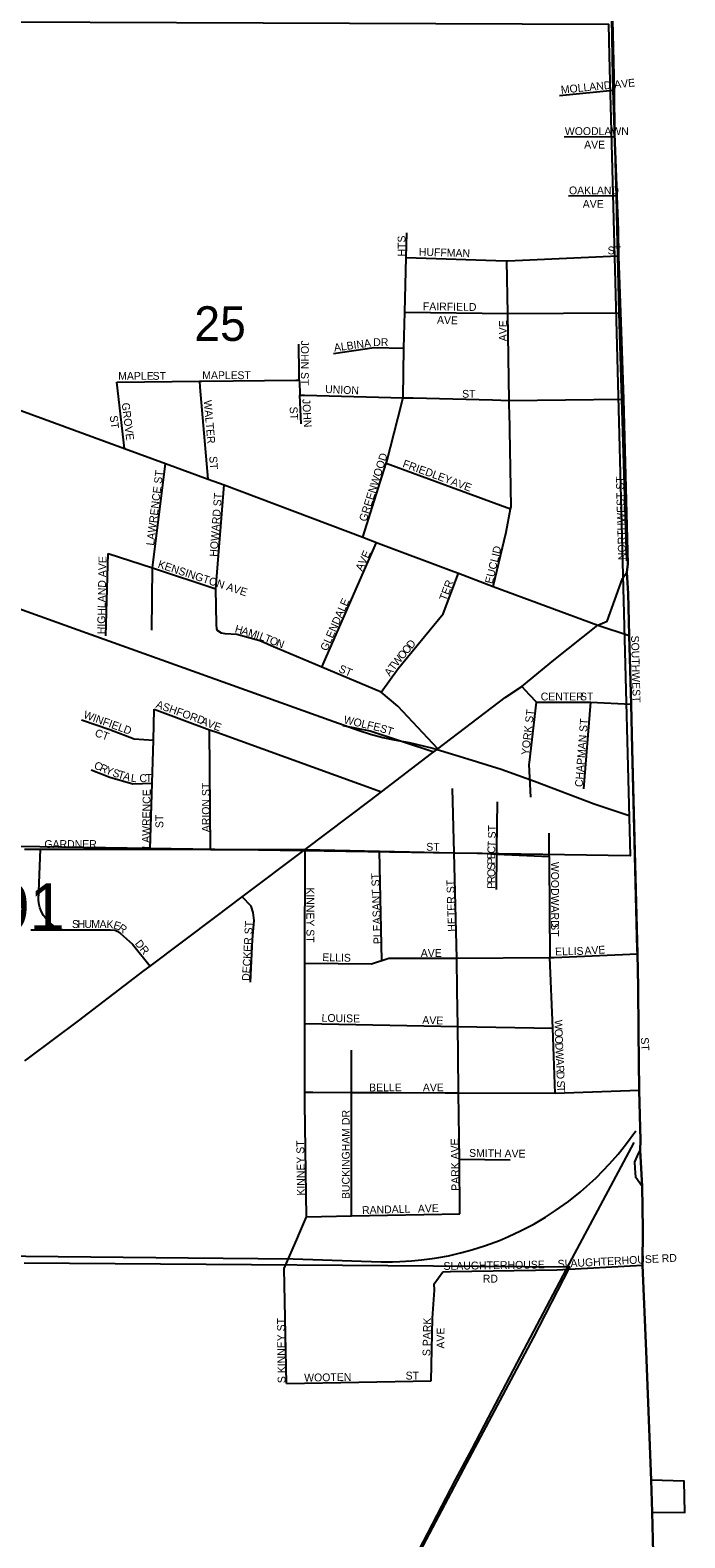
# Model space of a CAD drawing. Extents: x 1588073 to 2013523, y 1090242 to 1357120.
# Drawn here: x 1870959 to 1875138, y 1186996 to 1196618 of the extents above; entities that cross this region are included whole.
import ezdxf

# ---------------------------------------------------------------- set-up
doc = ezdxf.new("R2010")
doc.units = 0
for name, color, linetype in [('GM_X_Adjacent_County', 7, 'Continuous'), ('GM_X_City_Street', 7, 'Continuous'), ('GM_X_City_Street_Text', 7, 'Continuous'), ('GM_X_Corporation', 7, 'Continuous'), ('GM_X_County', 7, 'Continuous'), ('GM_X_County_Road_Text', 7, 'Continuous'), ('GM_X_Rail_Line', 7, 'Continuous'), ('GM_X_Section', 7, 'Continuous'), ('GM_X_Section_Text', 7, 'Continuous'), ('GM_X_State_Route', 7, 'Continuous'), ('GM_X_Township', 7, 'Continuous'), ('GM_X_Township_Subdivision', 7, 'Continuous'), ('GM_X_Township_Subdivision_Text', 7, 'Continuous'), ('GM_X_US_Route', 7, 'Continuous')]:
    doc.layers.add(name, color=color, linetype=linetype)

msp = doc.modelspace()

# ---------------------------------------------------------------- linework, layer by layer
at = {"layer": 'GM_X_Adjacent_County'}
msp.add_lwpolyline([(1874941.8, 1186640.9), (1874928.7, 1187160.7), (1874923.1, 1187364.9), (1874891.8, 1188188.1), (1874868.6, 1188735.8), (1874869, 1188969.3), (1874865.1, 1189239.2), (1874853.3, 1189471.1), (1874854.7, 1189533.5), (1874845.4, 1189851), (1874842.8, 1190228.3), (1874840.7, 1190513.7), (1874834.9, 1190722.6), (1874802.4, 1192031.4), (1874794.6, 1192317.6), (1874782.4, 1192755.6), (1874775.3, 1193023.2), (1874768.5, 1193158.1), (1874773.4, 1193209.6), (1874747.1, 1194263.8), (1874727.1, 1194819.2), (1874714.3, 1195175.2), (1874711.9, 1195341.1), (1874703.6, 1195559.3), (1874702.4, 1195623.6), (1874689.1, 1195958.2), (1874687.1, 1196230.8), (1874684.9, 1196324.1), (1874676.2, 1196684.8)], dxfattribs=at)
at = {"layer": 'GM_X_City_Street'}
for points in [[(1874768, 1193232), (1874736.3, 1194263.9), (1874719.1, 1194813.2), (1874709.8, 1195178.2), (1874705.4, 1195348.6), (1874700.7, 1195562.6), (1874698.8, 1195622.6), (1874690.4, 1195938.5), (1874689.3, 1195978.9), (1874681.4, 1196235.5), (1874678.7, 1196322.5), (1874670.9, 1196695.4)], [(1874338.9, 1196200.5), (1874681.4, 1196235.5)], [(1874368.4, 1195937.4), (1874690.4, 1195938.5)], [(1874396.1, 1195559.7), (1874700.7, 1195562.6)], [(1873336.3, 1194259.6), (1873339.6, 1194272.3), (1873340.5, 1194275.7), (1873344.2, 1194587.9), (1873350.3, 1194817.8), (1873359.4, 1195166.8), (1873363.6, 1195323.6)], [(1873359.4, 1195166.8), (1873996.2, 1195146.7), (1874001.5, 1195146.5), (1874007.8, 1195146.8)], [(1874017.6, 1194205.5), (1874016.7, 1194255.2), (1874007.3, 1194808.7), (1874001.5, 1195146.5)], [(1874007.8, 1195146.8), (1874709.8, 1195178.2)], [(1873350.3, 1194817.8), (1874007.3, 1194808.7), (1874719.1, 1194813.2)], [(1872676.5, 1194383.8), (1872675.9, 1194429.6), (1872673.6, 1194613.2)], [(1872894.3, 1194554.9), (1873155.3, 1194592.9), (1873344.2, 1194587.9)], [(1871513, 1194371), (1872042.1, 1194378.2)], [(1871561.6, 1193948.1), (1871513, 1194371)], [(1872096.1, 1193752.3), (1872043.1, 1194340.6), (1872042.1, 1194378.2), (1872053.9, 1194378.3)], [(1872053.9, 1194378.3), (1872654.9, 1194383.6), (1872676.5, 1194383.8), (1872677.3, 1194366.5)], [(1872677.3, 1194366.5), (1872680.4, 1194299.5), (1872680.9, 1194288.9), (1872710, 1194288.2)], [(1872689.4, 1194105.2), (1872680.9, 1194288.9)], [(1872710, 1194288.2), (1873339.6, 1194272.3), (1873367.8, 1194271.6), (1873403.1, 1194270.7)], [(1873083.5, 1193383), (1873231.2, 1193853.9), (1873236.1, 1193865.9), (1873328.9, 1194230.2), (1873336.3, 1194259.6)], [(1873403.1, 1194270.7), (1873909.9, 1194257.9), (1874016.7, 1194255.2), (1874736.3, 1194263.9)], [(1873915.3, 1193068), (1873997.9, 1193413.6), (1874025.7, 1193562.3), (1874028.3, 1193576.3), (1874017.9, 1194188.4), (1874017.6, 1194205.5)], [(1871736.5, 1192788.6), (1871740.2, 1193185.8), (1871823.2, 1193851.6)], [(1873231.2, 1193853.9), (1874025.7, 1193562.3)], [(1872149.4, 1192827.8), (1872144.9, 1193053.3), (1872197.4, 1193716.2)], [(1871441.4, 1192752.6), (1871456.5, 1193278.7)], [(1871456.5, 1193278.7), (1871740.2, 1193185.8), (1872144.9, 1193053.3)], [(1872820.3, 1192553.2), (1873169.8, 1193348.9)], [(1873200.5, 1192392.7), (1873307.6, 1192544.6), (1873594.2, 1192892.3), (1873692.5, 1193153.3)], [(1874582.2, 1192821.4), (1874641.4, 1192845.6), (1874739.4, 1193119.3), (1874768.3, 1193159.8)], [(1872512.3, 1192682.8), (1872424.5, 1192719.8), (1872278.1, 1192760.5), (1872203.9, 1192764.8), (1872179.8, 1192768.9), (1872157.4, 1192784.1), (1872150, 1192794.3), (1872149.4, 1192827.8)], [(1874834.2, 1190748.9), (1874802.4, 1192031.4), (1874794.6, 1192317.6), (1874782.4, 1192755.6)], [(1873560.5, 1192032), (1873305.5, 1192304.7), (1873200.5, 1192392.7), (1872820.3, 1192553.2), (1872537.9, 1192672), (1872512.3, 1192682.8)], [(1874098, 1192428.8), (1874144.3, 1192378.4), (1874190.4, 1192330.1), (1874213.7, 1192330)], [(1874146, 1191944.3), (1874190.4, 1192330.1)], [(1874213.7, 1192330), (1874538.1, 1192328.9), (1874794.6, 1192317.6)], [(1874492.3, 1191776.8), (1874538.1, 1192328.9)], [(1871285.7, 1192216.6), (1871468.3, 1192154.2), (1871622.7, 1192095.9), (1871745.8, 1192087.3)], [(1871725.6, 1191390.4), (1871737.9, 1191812.6), (1871745.8, 1192087.3), (1871751.5, 1192284.6)], [(1871751.5, 1192284.6), (1872104.5, 1192153.8), (1872149.6, 1192137.5), (1872150.6, 1192137.1)], [(1872111, 1191390), (1872104.5, 1192153.8)], [(1872150.6, 1192137.1), (1873200.6, 1191756.6)], [(1872955.6, 1192179.4), (1873130.2, 1192147.1), (1873535.1, 1192012.7)], [(1874154.9, 1191722.8), (1874144.7, 1191932.5), (1874146, 1191944.3)], [(1871347.3, 1191897.3), (1871467.6, 1191851), (1871614.1, 1191808.7), (1871737.9, 1191812.6)], [(1873683.2, 1190695), (1873665.8, 1191368.6), (1873655.3, 1191779.3)], [(1873938.2, 1191388.3), (1873938.2, 1191388.3), (1873942.2, 1191692.8)], [(1874271.9, 1191345), (1874270.9, 1191493.8)], [(1870923.2, 1191391.2), (1871025.1, 1191391.1), (1871725.6, 1191390.4), (1872111, 1191390), (1872714.4, 1191389.4)], [(1871162.5, 1190877.3), (1871138.7, 1190885), (1871114.6, 1190898), (1871084.9, 1190920.1), (1871062.8, 1190942.8), (1871043.8, 1190968.9), (1871033.5, 1190987.3), (1871027, 1191003), (1871020.6, 1191019.3), (1871016.1, 1191036), (1871011.3, 1191066.6), (1871025.1, 1191391.1)], [(1872712.2, 1190054.2), (1872712.2, 1190060), (1872712.6, 1190278), (1872713.2, 1190663.5), (1872714.4, 1191389.4)], [(1872714.4, 1191389.4), (1873189, 1191379), (1873665.8, 1191368.6), (1873844.4, 1191364.7), (1873937.9, 1191360.4), (1874271.9, 1191345), (1874272.1, 1191324), (1874272.3, 1191309.7)], [(1873204.1, 1190681.1), (1873189, 1191379)], [(1873935, 1191134.6), (1873937.9, 1191360.4), (1873938.2, 1191388.3)], [(1874272.3, 1191309.7), (1874277.2, 1190699.3), (1874282.5, 1190699.4), (1874304.2, 1190700.3)], [(1872366.2, 1190543.2), (1872379, 1190814.5), (1872388.4, 1190937), (1872382.9, 1190987.2), (1872369.5, 1191026.5), (1872312.5, 1191086.8)], [(1870963.8, 1190877.4), (1871133.2, 1190877.3), (1871162.5, 1190877.3), (1871256.9, 1190877.2), (1871471.7, 1190877.1), (1871501.1, 1190875.3), (1871513.4, 1190868.3), (1871535.8, 1190853), (1871611.9, 1190784.7), (1871724.7, 1190644.6)], [(1872713.2, 1190663.5), (1873137.1, 1190659.2), (1873181.8, 1190673.8)], [(1873181.8, 1190673.8), (1873182.3, 1190674), (1873204.1, 1190681.1), (1873247.6, 1190695.3), (1873683.2, 1190695), (1874277.2, 1190699.3)], [(1873685.6, 1190491.2), (1873683.2, 1190695)], [(1874309.6, 1189832.1), (1874295.3, 1190249), (1874277.2, 1190699.3)], [(1874304.2, 1190700.3), (1874834.9, 1190722.6)], [(1874845.4, 1189851), (1874842.8, 1190228.3), (1874840.7, 1190513.7), (1874834.9, 1190722.6), (1874834.2, 1190748.9)], [(1873690.5, 1190083.6), (1873688.4, 1190260.1), (1873685.6, 1190490.9), (1873685.6, 1190491.2)], [(1872712.6, 1190278), (1873688.4, 1190260.1), (1874295.3, 1190249)], [(1873009.1, 1189050.8), (1873009.4, 1189836.5), (1873009.5, 1190109.1)], [(1872762.8, 1189837.8), (1872711.8, 1189838.1), (1872712.2, 1190054.2)], [(1873701.9, 1189064.5), (1873698.5, 1189413.9), (1873693.5, 1189833.9), (1873690.5, 1190082.5), (1873690.5, 1190083.6)], [(1872671.7, 1188926.5), (1872722.3, 1189045.1), (1872712.8, 1189766.7), (1872711.8, 1189838.1)], [(1873243.5, 1189835.2), (1873234.3, 1189835.2), (1873009.4, 1189836.5), (1872762.8, 1189837.8)], [(1873617.3, 1189834.1), (1873607.4, 1189834.1), (1873243.5, 1189835.2)], [(1874845.4, 1189851), (1874309.6, 1189832.1), (1873693.5, 1189833.9), (1873617.3, 1189834.1)], [(1874822.3, 1189327.2), (1874820.5, 1189353.2), (1874819.2, 1189395.1), (1874834.9, 1189434.4), (1874853.3, 1189471.1)], [(1873698.5, 1189413.9), (1874023.7, 1189407.7)], [(1874865, 1189239.2), (1874824.4, 1189296.9), (1874822.3, 1189327.2)], [(1872722.3, 1189045.1), (1873009.1, 1189050.8), (1873701.9, 1189064.5)], [(1872581.2, 1188714.5), (1872666.7, 1188914.8), (1872671.7, 1188926.5)], [(1874321.7, 1188705.8), (1874868.6, 1188735.8)]]:
    msp.add_lwpolyline(points, dxfattribs=at)
at = {"layer": 'GM_X_Corporation'}
msp.add_lwpolyline([(1873309.7, 1186648.6), (1873745.9, 1187473.6), (1874171.5, 1188271.9), (1874404.4, 1188724.6), (1870921.3, 1188749.5)], dxfattribs=at)
msp.add_lwpolyline([(1874923.1, 1187364.9), (1874928.7, 1187160.7), (1875138, 1187158.2), (1875133, 1187358)], close=True, dxfattribs=at)
at = {"layer": 'GM_X_County'}
msp.add_lwpolyline([(1874676.2, 1196684.8), (1874684.9, 1196324.1), (1874687.1, 1196230.8), (1874689.1, 1195958.2), (1874702.4, 1195623.6), (1874703.6, 1195559.3), (1874711.9, 1195341.1), (1874714.3, 1195175.2), (1874727.1, 1194819.2), (1874747.1, 1194263.8), (1874773.4, 1193209.6), (1874768.5, 1193158.1), (1874775.3, 1193023.2), (1874782.4, 1192755.6), (1874794.6, 1192317.6), (1874802.4, 1192031.4), (1874834.9, 1190722.6), (1874840.7, 1190513.7), (1874842.8, 1190228.3), (1874845.4, 1189851), (1874854.7, 1189533.5), (1874853.3, 1189471.1), (1874865.1, 1189239.2), (1874869, 1188969.3), (1874868.6, 1188735.8), (1874891.8, 1188188.1), (1874923.1, 1187364.9), (1874928.7, 1187160.7), (1874941.8, 1186640.9)], dxfattribs=at)
at = {"layer": 'GM_X_Rail_Line'}
for points in [[(1864332, 1195255.1), (1865831.5, 1194720.4), (1867204.8, 1194231.1), (1868410.9, 1193799.5), (1869012.5, 1193586), (1869973, 1193254), (1871236.2, 1192802.4), (1872897.8, 1192205.3), (1873058.3, 1192148.8), (1873131.5, 1192124.7), (1873210.5, 1192104.7), (1873282.8, 1192088.9), (1873377.6, 1192071.4), (1873529, 1192034.9), (1873725.3, 1191976.6), (1873965.6, 1191901), (1874179.3, 1191825.3), (1874560.2, 1191679.8), (1874783.1, 1191606.4)], [(1870513.6, 1188797.7), (1871967.1, 1188784.1), (1872637.3, 1188776.3), (1873199.7, 1188758.4), (1873271.9, 1188758.4), (1873319.2, 1188759.3), (1873392.8, 1188764), (1873457.2, 1188769.5), (1873525.2, 1188778.3), (1873566.9, 1188785.3), (1873629.9, 1188796.8), (1873705.3, 1188814.4), (1873778.5, 1188833.9), (1873865.5, 1188861.2), (1873954.4, 1188894.5), (1874012.8, 1188918.6), (1874089.2, 1188954.7), (1874174.8, 1188998.7), (1874249.4, 1189043.6), (1874312.8, 1189084.8), (1874395.2, 1189143.2), (1874472.6, 1189204.3), (1874571.2, 1189293.7), (1874657.8, 1189383), (1874713.3, 1189445.5), (1874760.1, 1189505.3), (1874824.3, 1189594.8)], [(1872994.5, 1186111), (1873409.8, 1186859), (1873675, 1187365.8), (1873780, 1187564), (1873884.5, 1187764.4), (1874113, 1188197.5), (1874401.2, 1188748.1), (1874813.9, 1189518.8)]]:
    msp.add_lwpolyline(points, dxfattribs=at)
at = {"layer": 'GM_X_Section'}
msp.add_lwpolyline([(1869685.5, 1196674.9), (1874650.6, 1196655.9), (1874655.8, 1196454.6), (1874698.7, 1194770.3), (1874788.8, 1191348.3), (1869621.6, 1191428.1)], close=True, dxfattribs=at)
at = {"layer": 'GM_X_State_Route'}
for points in [[(1872714.4, 1191389.4), (1873128.4, 1191701.3), (1873200.6, 1191756.6), (1873520.7, 1192001.8), (1873535.1, 1192012.7), (1873560.5, 1192032), (1873991.1, 1192358.7), (1874098, 1192428.8), (1874301.3, 1192596.6), (1874582.2, 1192821.4)], [(1870925, 1190039.8), (1870947.8, 1190056.8), (1871267, 1190295.7), (1871687.3, 1190616.4), (1871724.7, 1190644.6), (1872145.6, 1190961.2), (1872312.5, 1191086.8), (1872714.4, 1191389.4)]]:
    msp.add_lwpolyline(points, dxfattribs=at)
at = {"layer": 'GM_X_Township'}
msp.add_lwpolyline([(1874676.2, 1196684.8), (1874684.9, 1196324.1), (1874687.1, 1196230.8), (1874689.1, 1195958.2), (1874702.4, 1195623.6), (1874703.6, 1195559.3), (1874711.9, 1195341.1), (1874714.3, 1195175.2), (1874727.1, 1194819.2), (1874747.1, 1194263.8), (1874773.4, 1193209.6), (1874768.5, 1193158.1), (1874775.3, 1193023.2), (1874782.4, 1192755.6), (1874794.6, 1192317.6), (1874802.4, 1192031.4), (1874834.9, 1190722.6), (1874840.7, 1190513.7), (1874842.8, 1190228.3), (1874845.4, 1189851), (1874854.7, 1189533.5), (1874853.3, 1189471.1), (1874865.1, 1189239.2), (1874869, 1188969.3), (1874868.6, 1188735.8), (1874891.8, 1188188.1), (1874923.1, 1187364.9), (1874928.7, 1187160.7), (1874941.8, 1186640.9)], dxfattribs=at)
at = {"layer": 'GM_X_Township_Subdivision'}
for points in [[(1872595.2, 1187981.4), (1872581.2, 1188714.5)], [(1873518.8, 1187998), (1873527, 1188397.6), (1873540.1, 1188576.3), (1873538.3, 1188616.5), (1873592.9, 1188694.6)], [(1873592.9, 1188694.6), (1873641.5, 1188695.3)], [(1873641.5, 1188695.3), (1873641.5, 1188695.3), (1874321.7, 1188705.8)], [(1872595.2, 1187981.4), (1873518.8, 1187998)]]:
    msp.add_lwpolyline(points, dxfattribs=at)
at = {"layer": 'GM_X_US_Route'}
for points in [[(1867194.8, 1195482.7), (1869695.5, 1194637.3), (1869866.9, 1194566.6), (1871050.4, 1194134.7)], [(1871050.4, 1194134.7), (1871561.6, 1193948.1), (1871823.2, 1193851.6), (1872096.1, 1193752.3), (1872197.4, 1193716.2), (1873083.5, 1193383), (1873169.8, 1193348.9), (1873179.9, 1193345.1)], [(1873179.9, 1193345.1), (1873663.3, 1193164.2)], [(1873663.3, 1193164.2), (1873692.5, 1193153.3), (1873915.3, 1193068), (1874582.2, 1192821.4)], [(1874582.2, 1192821.4), (1874782.4, 1192755.6)]]:
    msp.add_lwpolyline(points, dxfattribs=at)

# ---------------------------------------------------------------- texts
at = {"layer": 'GM_X_City_Street_Text'}
for s, rotation, p in [('MOLLAND AVE', 5.65359, (1874349, 1196212.4)), ('WOODLAWN', 0.00001, (1874371.9, 1195948.5)), ('AVE', 0.00001, (1874495.1, 1195862.4)), ('OAKLAND', 0.00001, (1874398.3, 1195570.1)), ('AVE', 0.00001, (1874486.3, 1195484.1)), ('HTS', 90, (1873354.9, 1195173.5)), ('HUFFMAN', 358.31466, (1873439.4, 1195178.5)), ('ST', 0.00001, (1874644.7, 1195187.3)), ('FAIRFIELD', 359.1935, (1873465.6, 1194830.9)), ('AVE', 358.02611, (1873555.3, 1194744.9)), ('AVE', 90, (1874001.6, 1194632.3)), ('JOHN ST', 270, (1872687.3, 1194636.7)), ('ALBINA', 7.66649, (1872901.1, 1194566.6)), ('DR', 0.00001, (1873148.7, 1194601.9)), ('MAPLE', 0.00001, (1871520.7, 1194386.5)), ('ST', 0.00001, (1871740.7, 1194386.5)), ('MAPLE', 0.00001, (1872057.5, 1194390.9)), ('ST', 0.00001, (1872281.9, 1194390.9)), ('UNION', 357.45407, (1872841.1, 1194302.9)), ('GROVE', 277.13007, (1871543.2, 1194237.4)), ('WALTER', 274.92438, (1872066.9, 1194254.7)), ('JOHN', 273.26871, (1872696.1, 1194263.2)), ('ST', 0.00001, (1873716.3, 1194272.1)), ('ST', 277.12166, (1871466.7, 1194156.4)), ('ST', 273.57422, (1872614.6, 1194213.9)), ('ST', 273.57422, (1872102.1, 1193898)), ('GREENWOOD', 72.37762, (1873104.5, 1193477.9)), ('FRIEDLEY', 339.94213, (1873332.3, 1193831.5)), ('LAWRENCE ST', 82.87441, (1871748.9, 1193326.6)), ('AVE', 340.34568, (1873640.3, 1193717.1)), ('NORTHWEST ST', 91.6357, (1874762.8, 1193237.2)), ('HOWARD ST', 85.81731, (1872153.7, 1193255.8)), ('AVE', 65.22379, (1873078.5, 1193162.2)), ('EUCLID', 76.23801, (1873909.5, 1193081.3)), ('HIGHLAND AVE', 88.90939, (1871436.5, 1192762.4)), ('KENSINGTON AVE', 341.86259, (1871770, 1193189.2)), ('TER', 69.45443, (1873615.1, 1192972.4)), ('GLENDALE', 66.19456, (1872854.1, 1192651.7)), ('H', 344.2348, (1872261.8, 1192775.9)), ('A', 343.21703, (1872303.9, 1192764)), ('M', 343.06529, (1872346, 1192751.3)), ('I', 342.4218, (1872396.3, 1192736)), ('L', 339.93637, (1872416.8, 1192729.5)), ('T', 338.38882, (1872449.5, 1192717.6)), ('O', 338.8622, (1872482.6, 1192704.4)), ('N', 340.17573, (1872524.9, 1192688.1)), ('O', 50.35678, (1873365.6, 1192632.1)), ('D', 50.32313, (1873393.7, 1192665.9)), ('SOUTHWEST', 271.3632, (1874794.9, 1192753.7)), ('W', 50.8413, (1873301.5, 1192553.9)), ('O', 50.36375, (1873337.6, 1192598.2)), ('ST', 336.80612, (1872923.6, 1192524.5)), ('A', 54.3937, (1873255.4, 1192490.5)), ('T', 53.42236, (1873280.9, 1192526.1)), ('ASHFORD', 340.16751, (1871757.1, 1192295.9)), ('CENTER', 0.00001, (1874217.9, 1192340.5)), ('ST', 0.00001, (1874468.7, 1192340.5)), ('WINFIELD', 339.94437, (1871295.1, 1192229.9)), ('A', 338.39538, (1872043.4, 1192190.2)), ('V', 338.39538, (1872084.3, 1192174)), ('WOLFE', 347.09151, (1872957.1, 1192195.1)), ('YORK ST', 83.23019, (1874142.5, 1191989)), ('CHAPMAN ST', 85.50533, (1874485.7, 1191786.2)), ('CT', 340.5566, (1871367.6, 1192113.6)), ('E', 340.04967, (1872126.7, 1192157.2)), ('ST', 341.57598, (1873186.8, 1192142)), ('C', 336.32611, (1871361.7, 1191908.5)), ('R', 336.34796, (1871398, 1191892.6)), ('Y', 337.77589, (1871435.5, 1191876.1)), ('S', 342.37019, (1871480.4, 1191858)), ('T', 343.41251, (1871514.9, 1191847.1)), ('A', 343.41801, (1871548.6, 1191837)), ('L', 352.76897, (1871599.5, 1191822.6)), ('C', 1.94313, (1871657.1, 1191818.5)), ('T', 2.04622, (1871696.7, 1191819.9)), ('LAWRENCE', 89.25634, (1871722.5, 1191394)), ('ARION ST', 90, (1872105.3, 1191499.5)), ('ST', 90, (1871808.5, 1191525.9)), ('ST', 90, (1873931.3, 1191459.9)), ('GARDNER', 0.00001, (1871049.9, 1191398.9)), ('T', 86.00781, (1873928, 1191401.8)), ('ST', 0.00001, (1873487.5, 1191381.3)), ('C', 88.4456, (1873927, 1191362.7)), ('E', 89.94534, (1873926.9, 1191327.9)), ('S', 89.99561, (1873926.9, 1191257.5)), ('O', 89.9642, (1873926.9, 1191213.5)), ('P', 90, (1873926.9, 1191292.7)), ('WOODWARD', 270, (1874284.5, 1191310.3)), ('PLEASANT ST', 91.88717, (1873200.9, 1190786.4)), ('HETER ST', 91.78891, (1873676.1, 1190865.6)), ('R', 89.95142, (1873926.9, 1191173.8)), ('P', 90, (1873926.9, 1191138.7)), ('KINNEY ST', 270, (1872722.5, 1191147.5)), ('S', 359.90442, (1871225.8, 1190888.5)), ('H', 359.88032, (1871261, 1190888.4)), ('U', 359.90796, (1871305.1, 1190888.3)), ('M', 359.89983, (1871349.1, 1190888.3)), ('A', 359.8861, (1871401.9, 1190888.2)), ('K', 357.40836, (1871445.3, 1190888.1)), ('E', 342.3558, (1871485.8, 1190886.7)), ('R', 324.40303, (1871515.7, 1190877.9)), ('DECKER ST', 86.94874, (1872360.5, 1190549.6)), ('ST', 270, (1874284.5, 1190918.7)), ('DR', 308.65981, (1871624.8, 1190788.2)), ('ELLIS', 1.50653, (1874310, 1190712.5)), ('AVE', 3.94312, (1874498.8, 1190716.9)), ('ELLIS', 358.49317, (1872823.4, 1190677.3)), ('AVE', 0.00001, (1873452.3, 1190703.7)), ('LOUISE', 358.83159, (1872818.9, 1190290.1)), ('AVE', 358.02611, (1873461.4, 1190276.9)), ('W', 270.43712, (1874306.5, 1190302.6)), ('O', 272.18524, (1874307, 1190243.7)), ('O', 272.4495, (1874308.7, 1190199.5)), ('D', 272.47881, (1874310.5, 1190155.5)), ('W', 272.45524, (1874312.4, 1190111.5)), ('ST', 273.57422, (1874856.5, 1190188.9)), ('A', 272.44874, (1874314.9, 1190054.4)), ('R', 272.46364, (1874316.8, 1190010.4)), ('D', 272.44874, (1874318.5, 1189970.9)), ('S', 272.44691, (1874320.9, 1189913.7)), ('BELLE', 0.00001, (1873122.3, 1189845.7)), ('AVE', 0.00001, (1873465.5, 1189845.7)), ('T', 272.44691, (1874322.5, 1189878.5)), ('BUCKINGHAM DR', 90, (1872998.5, 1189158.7)), ('KINNEY ST', 90.7844, (1872712.5, 1189180.5)), ('PARK AVE', 90.82986, (1873698.1, 1189211.3)), ('SMITH AVE', 359.23503, (1873760.4, 1189427.7)), ('RANDALL', 1.7349, (1873078, 1189062.5)), ('AVE', 1.9739, (1873434.4, 1189071.3)), ('SLAUGHTERHOUSE RD', 3.01256, (1874327.4, 1188719.3))]:
    msp.add_text(s, height=50, rotation=rotation, dxfattribs=at).set_placement(p)
at = {"layer": 'GM_X_County_Road_Text'}
msp.add_text('C-191', height=300, rotation=0.00001, dxfattribs=at).set_placement((1870086.3, 1190872.6))
at = {"layer": 'GM_X_Section_Text'}
msp.add_text('25', height=221, rotation=0.00001, dxfattribs=at).set_placement((1872006.9, 1194634.8))
at = {"layer": 'GM_X_Township_Subdivision_Text'}
for s, rotation, p in [('SLAUGHTERHOUSE', 0.8823, (1873597.7, 1188706.1)), ('RD', 0.00001, (1873848.3, 1188625.4)), ('S KINNEY ST', 90.6817, (1872589.3, 1187983.8)), ('S PARK', 88.80717, (1873513.3, 1188155.7)), ('AVE', 90, (1873603.7, 1188203.9)), ('WOOTEN', 0.95436, (1872708.5, 1187993.3)), ('ST', 0.00001, (1873355.5, 1188006.5))]:
    msp.add_text(s, height=50, rotation=rotation, dxfattribs=at).set_placement(p)

doc.saveas('drawing.dxf')
